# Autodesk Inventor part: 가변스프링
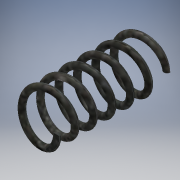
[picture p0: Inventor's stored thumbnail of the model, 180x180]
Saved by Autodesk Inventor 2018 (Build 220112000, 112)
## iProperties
Created: 2020-02
Part Number: 가변스프링
Material: 강철
Document SubType Name: Modeling
Designer: Administrator
Mass: 6.42998 g
Surface Area: 16.6202 cm^2
Volume: 0.819106 cm^3
Density: 7.85 g/cm^3
Appearance: 플레이트
Author: Administrator
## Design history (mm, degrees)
sketch "스케치1"
  geometry: L1 (0, 0)-(7, 0); L2 (7, 0)-(7, 35.5); L3 (7, 35.5)-(0, 35.5); L4 (0, 35.5)-(0, 0); C1 r 1 at (7, 0)
  constraints: 8 end point, 2 parallel, 1 centre point, 1 coincident, 1 horizontal, 1 perpendicular
  dimensions: "d0" = 35.5 distance of L3.end L1.start (derived); "d1" = 2 diameter of C1; "d2" = 14 diameter of L1.end L4
feature "코일1" sketch "스케치1" pitch "d3" = 10; turns "d5" = 6; dims "d4" = 35.5 (= d0), "d6" = 0, angle "d7" = 90 deg, angle "d8" = 90 deg, "d9" = 0, "d10" = 0
sketch "스케치2"
  geometry: L1 (-8, 0)-(-6, 0) reference; 1 further point
  constraints: 1 horizontal alignment
extrude "돌출1" cut sketch "스케치2" extent not by distance; stored distance "d11" = 10; taper "d12" = 0 deg
node "작업 평면1"
sketch "스케치3"
  geometry: L1 (8, 0)-(6, 0) reference; 1 further point
  constraints: 1 horizontal alignment
extrude "돌출2" cut sketch "스케치3" extent not by distance; stored distance "d13" = 10; taper "d14" = 0 deg
node "솔리드1"
node "절단 모서리 투영1"
node "절단 모서리 투영2"
